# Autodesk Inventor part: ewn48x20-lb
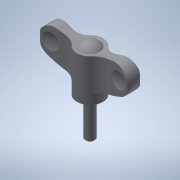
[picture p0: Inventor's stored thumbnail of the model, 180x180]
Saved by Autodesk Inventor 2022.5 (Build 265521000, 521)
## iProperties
Created: 2016-12
Part Number: ewn48x20-lb
Material: 一般
Document SubType Name: Modeling
Designer: imaocorp
Density: 1 g/cm^3
Appearance: 既定
Author: imaocorp
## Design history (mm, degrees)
node "ewn48x20-lb.x_t1"
node "ewn48x20-lb"
node "Base1"
